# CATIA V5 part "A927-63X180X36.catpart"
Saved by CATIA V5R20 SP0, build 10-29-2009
Part number: A927-63X180X36
Source: Unknown
Property "A": "36.000"
Property "ARTICLENO": "A927-63X180X36"
Property "BOMINFO": "A927-63X180X36"
Property "CODE": "A927-63X180X36"
Property "CREATOR": "CADENAS GmbH"
Property "D": "14.000"
Property "D1": "20.000"
Property "F": "18.000"
Property "FORM": "A"
Property "L": "180.000"
Property "L1": "90.000"
Property "L2": "20.000"
Property "L3": "50.000"
Property "LINA": "A927-63X180X36"
Property "NB": "A927-63X180X36"
Property "NBSYN": "$CODE."
Property "NN": "A927"
Property "NT": "VDI 3387 Removable Die Heels, steel and self-lubricating"
Property "R": "16.000"
Property "S": "36.000"
Property "SUPPLIER": "CF"
Property "T": "16.000"
Property "W": "63.000"
Bounding box of the stored display mesh (mm): x -31.5 to 31.5, y 0 to 180, z -36 to 0
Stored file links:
  C:\Users\borellobunino\Desktop\3D X SITO CF\A927\GSB_OILLESS_G2290506318036\CATIAV5\A927-63X180X36.catpart
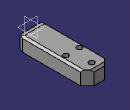
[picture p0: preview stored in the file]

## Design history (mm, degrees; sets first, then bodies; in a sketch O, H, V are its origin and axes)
Body1 "Geometry.1" (main body)
  Solid1 "A927-63X180X36.catpart": solid without history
